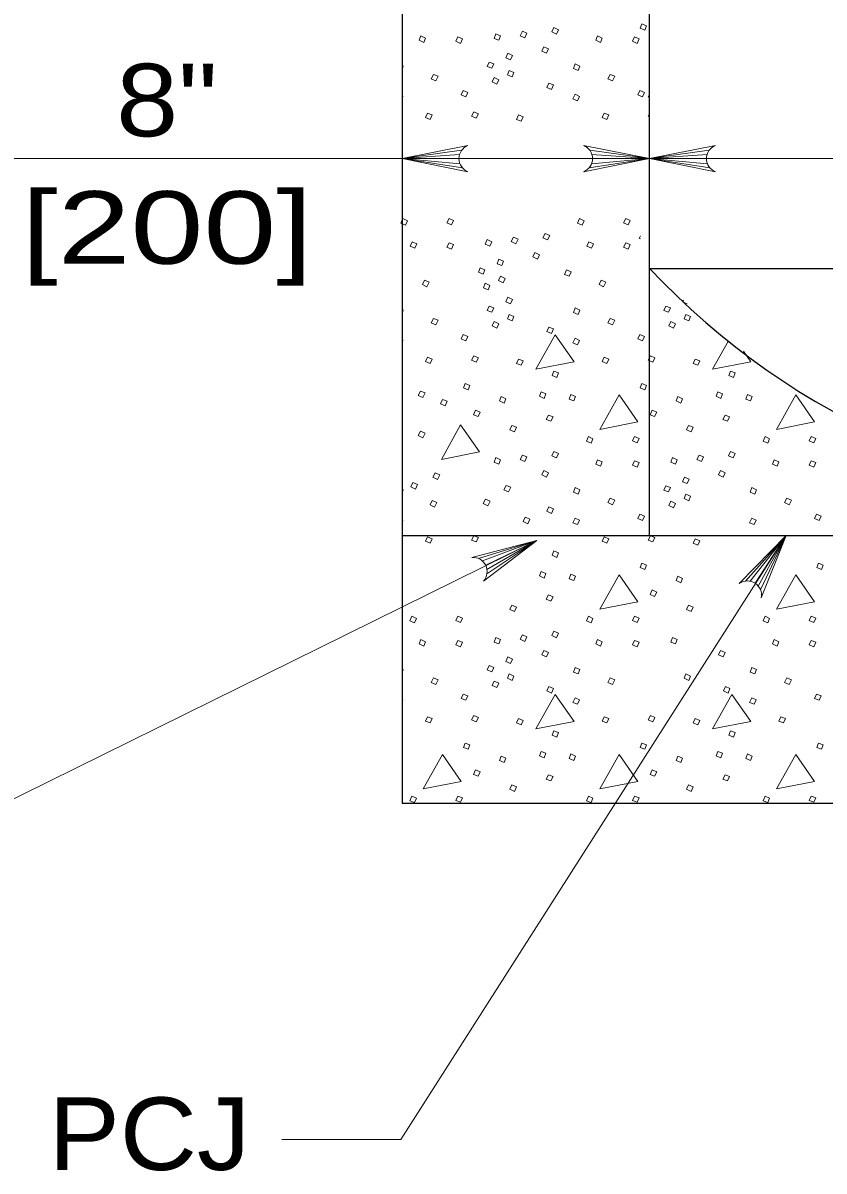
# Model space of a CAD drawing. Extents: x 1083.1 to 1123, y 697.4 to 741.4.
# Drawn here: x 1091.72 to 1093.443, y 720.889 to 723.357 of the extents above; entities that cross this region are included whole.
import ezdxf
from ezdxf.enums import TextEntityAlignment as Align

# ---------------------------------------------------------------- set-up
doc = ezdxf.new("R2010")
doc.units = 0
doc.header["$LTSCALE"] = 0.062
doc.layers.add('1', color=7, linetype='Continuous', lineweight=13)

msp = doc.modelspace()

# ---------------------------------------------------------------- linework, layer by layer
at = {"layer": '1', "lineweight": 25}
for p, q in [((1093.0675, 722.82933), (1093.0675, 724.8505)), ((1093.0675, 722.82933), (1095.442, 722.82933)), ((1093.0675, 722.25542), (1093.0675, 722.82933)), ((1092.53542, 722.25542), (1095.96625, 722.25542))]:
    msp.add_line(p, q, dxfattribs=at)
at = {"layer": '1'}
for p, q in [((1091.67708, 723.06533), (1093.0675, 723.06533)), ((1092.66358, 723.08333), (1092.53542, 723.06533)), ((1092.65925, 723.07442), (1092.53542, 723.06533)), ((1092.65792, 723.06533), (1092.53542, 723.06533)), ((1092.66017, 723.05383), (1092.53542, 723.06533)), ((1092.66508, 723.0455), (1092.53542, 723.06533)), ((1092.93775, 723.0455), (1093.0675, 723.06533)), ((1092.93933, 723.08333), (1093.0675, 723.06533)), ((1092.94267, 723.05383), (1093.0675, 723.06533)), ((1092.94367, 723.07442), (1093.0675, 723.06533)), ((1092.945, 723.06533), (1093.0675, 723.06533)), ((1093.19567, 723.08333), (1093.0675, 723.06533)), ((1093.19133, 723.07442), (1093.0675, 723.06533)), ((1095.442, 723.06533), (1093.0675, 723.06533)), ((1093.19, 723.06533), (1093.0675, 723.06533)), ((1093.19225, 723.05383), (1093.0675, 723.06533)), ((1093.19717, 723.0455), (1093.0675, 723.06533)), ((1093.361, 722.25542), (1092.53317, 720.95708)), ((1093.27392, 722.15733), (1093.361, 722.25542)), ((1093.28358, 722.15692), (1093.361, 722.25542)), ((1093.29442, 722.15258), (1093.361, 722.25542)), ((1093.30133, 722.14658), (1093.361, 722.25542)), ((1093.30642, 722.13808), (1093.361, 722.25542)), ((1092.70017, 722.20583), (1092.8255, 722.24467)), ((1092.70817, 722.2005), (1092.8255, 722.24467)), ((1092.71525, 722.19117), (1092.8255, 722.24467)), ((1092.718, 722.18242), (1092.8255, 722.24467)), ((1092.718, 722.1725), (1092.8255, 722.24467)), ((1092.53317, 720.95708), (1092.27733, 720.95708))]:
    msp.add_line(p, q, dxfattribs=at)
at = {"layer": '1', "lineweight": 25}
msp.add_lwpolyline([(1093.0675, 725.37967), (1092.53542, 725.37967), (1092.53542, 721.67958), (1095.96625, 721.67958), (1095.96625, 725.37967)], dxfattribs=at)
at = {"layer": '1'}
for points in [[(1092.79408, 723.33892), (1092.80408, 723.33492), (1092.79942, 723.32492), (1092.78942, 723.32958)], [(1092.86208, 723.34692), (1092.87208, 723.34225), (1092.86742, 723.33292), (1092.85742, 723.33758)], [(1093.05133, 723.35483), (1093.06133, 723.35083), (1093.05733, 723.3415), (1093.04733, 723.3455)], [(1092.57617, 723.32892), (1092.58617, 723.32425), (1092.58217, 723.315), (1092.57217, 723.31958)], [(1092.6555, 723.32692), (1092.6655, 723.32292), (1092.66083, 723.313), (1092.65083, 723.31758)], [(1092.73742, 723.33358), (1092.74742, 723.32892), (1092.74342, 723.31958), (1092.73342, 723.32367)], [(1092.956, 723.32892), (1092.966, 723.32425), (1092.962, 723.315), (1092.952, 723.31958)], [(1093.03533, 723.32692), (1093.04533, 723.32292), (1093.04067, 723.313), (1093.03067, 723.31758)], [(1092.76275, 723.29167), (1092.77275, 723.287), (1092.76875, 723.27767), (1092.75875, 723.28167)], [(1092.84008, 723.30567), (1092.85008, 723.301), (1092.84608, 723.29167), (1092.83608, 723.29633)], [(1092.72275, 723.273), (1092.73275, 723.269), (1092.72875, 723.25967), (1092.71875, 723.26367)], [(1092.908, 723.269), (1092.918, 723.26433), (1092.914, 723.255), (1092.904, 723.259)], [(1092.60283, 723.24633), (1092.61283, 723.24233), (1092.60817, 723.23233), (1092.59817, 723.237)], [(1092.73342, 723.23967), (1092.74342, 723.235), (1092.73942, 723.22567), (1092.72942, 723.23033)], [(1092.76608, 723.255), (1092.77608, 723.25033), (1092.77208, 723.241), (1092.76208, 723.24567)], [(1092.98267, 723.24633), (1092.99267, 723.24233), (1092.988, 723.23233), (1092.978, 723.237)], [(1092.85075, 723.22767), (1092.86075, 723.22367), (1092.85675, 723.21367), (1092.84675, 723.21833)], [(1092.66683, 723.21167), (1092.67683, 723.20767), (1092.67283, 723.19833), (1092.66283, 723.20233)], [(1092.90733, 723.20367), (1092.91733, 723.199), (1092.91267, 723.18967), (1092.90267, 723.19367)], [(1093.04667, 723.21167), (1093.05667, 723.20767), (1093.05267, 723.19833), (1093.04267, 723.20233)], [(1092.6895, 723.16575), (1092.6995, 723.16175), (1092.69483, 723.15242), (1092.68483, 723.15642)], [(1092.59017, 723.16308), (1092.60017, 723.15908), (1092.59617, 723.14975), (1092.58617, 723.15375)], [(1092.78608, 723.15908), (1092.79608, 723.15508), (1092.79142, 723.14575), (1092.78142, 723.14975)], [(1092.97, 723.16308), (1092.98, 723.15908), (1092.976, 723.14975), (1092.966, 723.15375)], [(1092.53708, 722.9365), (1092.54708, 722.93183), (1092.54308, 722.9225), (1092.53308, 722.9265)], [(1092.63642, 722.9365), (1092.64642, 722.9325), (1092.64175, 722.92317), (1092.63175, 722.92717)], [(1092.91692, 722.9365), (1092.92692, 722.93183), (1092.92292, 722.9225), (1092.91292, 722.9265)], [(1093.01625, 722.9365), (1093.02617, 722.9325), (1093.02158, 722.92317), (1093.01158, 722.92717)], [(1092.775, 722.8965), (1092.785, 722.8925), (1092.78033, 722.8825), (1092.77033, 722.88717)], [(1092.843, 722.9045), (1092.85292, 722.89983), (1092.84833, 722.8905), (1092.83833, 722.89517)], [(1092.55708, 722.8865), (1092.56708, 722.88183), (1092.56308, 722.8725), (1092.55308, 722.87717)], [(1092.63642, 722.8845), (1092.64642, 722.8805), (1092.64175, 722.8705), (1092.63175, 722.87517)], [(1092.71833, 722.89117), (1092.72833, 722.8865), (1092.72433, 722.87717), (1092.71433, 722.88117)], [(1092.93692, 722.8865), (1092.94692, 722.88183), (1092.94292, 722.8725), (1092.93292, 722.87717)], [(1093.01625, 722.8845), (1093.02617, 722.8805), (1093.02158, 722.8705), (1093.01158, 722.87517)], [(1092.74367, 722.84925), (1092.75367, 722.84458), (1092.74967, 722.83525), (1092.73967, 722.83925)], [(1092.821, 722.86317), (1092.831, 722.8585), (1092.827, 722.84925), (1092.817, 722.85392)], [(1092.70367, 722.83058), (1092.71367, 722.82658), (1092.70967, 722.81725), (1092.69967, 722.82125)], [(1092.88892, 722.82658), (1092.89892, 722.82192), (1092.89492, 722.81258), (1092.88492, 722.81658)], [(1092.58375, 722.80392), (1092.59375, 722.79992), (1092.58908, 722.78992), (1092.57908, 722.79458)], [(1092.71433, 722.79725), (1092.72433, 722.79258), (1092.72033, 722.78325), (1092.71033, 722.78792)], [(1092.747, 722.81258), (1092.757, 722.80792), (1092.753, 722.79858), (1092.743, 722.80325)], [(1092.96358, 722.80392), (1092.97358, 722.79992), (1092.96892, 722.78992), (1092.95892, 722.79458)], [(1092.72275, 722.7485), (1092.73275, 722.7445), (1092.72875, 722.73517), (1092.71875, 722.73917)], [(1092.76275, 722.76717), (1092.77275, 722.7625), (1092.76875, 722.75317), (1092.75875, 722.75717)], [(1092.908, 722.7445), (1092.918, 722.73983), (1092.914, 722.7305), (1092.904, 722.7345)], [(1093.10258, 722.7485), (1093.11258, 722.7445), (1093.10858, 722.73517), (1093.09858, 722.73917)], [(1092.60283, 722.72183), (1092.61283, 722.71783), (1092.60817, 722.70783), (1092.59817, 722.7125)], [(1092.76608, 722.7305), (1092.77608, 722.72583), (1092.77208, 722.7165), (1092.76208, 722.72117)], [(1092.98267, 722.72183), (1092.99267, 722.71783), (1092.988, 722.70783), (1092.978, 722.7125)], [(1093.14592, 722.7305), (1093.15592, 722.72583), (1093.15192, 722.7165), (1093.14192, 722.72117)], [(1092.73342, 722.71517), (1092.74342, 722.7105), (1092.73942, 722.70117), (1092.72942, 722.70583)], [(1092.85075, 722.70317), (1092.86075, 722.69917), (1092.85675, 722.68917), (1092.84675, 722.69383)], [(1093.11325, 722.71517), (1093.12325, 722.7105), (1093.11925, 722.70117), (1093.10925, 722.70583)], [(1092.66683, 722.68717), (1092.67683, 722.68317), (1092.67283, 722.67383), (1092.66283, 722.67783)], [(1092.86475, 722.6865), (1092.82342, 722.61258), (1092.90533, 722.62858)], [(1092.90733, 722.67917), (1092.91733, 722.6745), (1092.91267, 722.66525), (1092.90267, 722.66917)], [(1093.04667, 722.68717), (1093.05667, 722.68317), (1093.05267, 722.67383), (1093.04267, 722.67783)], [(1092.59017, 722.63858), (1092.60017, 722.63458), (1092.59617, 722.62525), (1092.58617, 722.62925)], [(1092.6895, 722.64125), (1092.6995, 722.63725), (1092.69483, 722.62792), (1092.68483, 722.63192)], [(1092.78608, 722.63458), (1092.79608, 722.63058), (1092.79142, 722.62125), (1092.78142, 722.62525)], [(1092.97, 722.63858), (1092.98, 722.63458), (1092.976, 722.62525), (1092.966, 722.62925)], [(1093.06933, 722.64125), (1093.07925, 722.63725), (1093.07458, 722.62792), (1093.06458, 722.63192)], [(1093.16592, 722.63458), (1093.17592, 722.63058), (1093.17125, 722.62125), (1093.16125, 722.62525)], [(1092.86208, 722.60858), (1092.87208, 722.60458), (1092.86808, 722.59458), (1092.85808, 722.59925)], [(1093.24192, 722.60858), (1093.25183, 722.60458), (1093.24783, 722.59458), (1093.23783, 722.59925)], [(1092.6715, 722.58192), (1092.6815, 722.57792), (1092.6775, 722.56858), (1092.6675, 722.57258)], [(1093.05133, 722.58192), (1093.06133, 722.57792), (1093.05733, 722.56858), (1093.04733, 722.57258)], [(1092.57483, 722.56567), (1092.58483, 722.56167), (1092.58017, 722.55167), (1092.57017, 722.55633)], [(1092.6225, 722.54783), (1092.6325, 722.54383), (1092.62783, 722.53383), (1092.61783, 722.5385)], [(1092.74875, 722.55392), (1092.75875, 722.54925), (1092.75475, 722.53992), (1092.74475, 722.54458)], [(1092.83475, 722.56392), (1092.84475, 722.55992), (1092.84075, 722.54992), (1092.83075, 722.55458)], [(1092.89867, 722.55858), (1092.90867, 722.55392), (1092.90467, 722.54458), (1092.89467, 722.54858)], [(1093.002, 722.55725), (1092.96067, 722.48333), (1093.04267, 722.49933)], [(1093.12858, 722.55392), (1093.13858, 722.54925), (1093.13458, 722.53992), (1093.12458, 722.54458)], [(1093.21458, 722.56392), (1093.22458, 722.55992), (1093.22058, 722.54992), (1093.21058, 722.55458)], [(1093.2785, 722.55858), (1093.2885, 722.55392), (1093.2845, 722.54458), (1093.2745, 722.54858)], [(1093.38183, 722.55725), (1093.3405, 722.48333), (1093.42242, 722.49933)], [(1092.6935, 722.52458), (1092.7035, 722.52), (1092.69883, 722.51067), (1092.68883, 722.51467)], [(1093.07325, 722.52458), (1093.08325, 722.52), (1093.07858, 722.51067), (1093.06858, 722.51467)], [(1092.85008, 722.51392), (1092.86008, 722.51), (1092.85542, 722.50067), (1092.84542, 722.50467)], [(1093.22992, 722.51392), (1093.23983, 722.51), (1093.23525, 722.50067), (1093.22525, 722.50467)], [(1092.57483, 722.47925), (1092.58483, 722.47525), (1092.58017, 722.46525), (1092.57017, 722.46992)], [(1092.66133, 722.49283), (1092.62008, 722.41883), (1092.702, 722.43483)], [(1092.77142, 722.492), (1092.78142, 722.488), (1092.77742, 722.478), (1092.76742, 722.48267)], [(1093.15125, 722.492), (1093.16125, 722.488), (1093.15725, 722.478), (1093.14725, 722.48267)], [(1092.936, 722.468), (1092.946, 722.46333), (1092.942, 722.454), (1092.932, 722.458)], [(1093.03533, 722.468), (1093.04533, 722.464), (1093.04067, 722.45467), (1093.03067, 722.45867)], [(1093.31583, 722.468), (1093.32583, 722.46333), (1093.32183, 722.454), (1093.31183, 722.458)], [(1093.41517, 722.468), (1093.42508, 722.464), (1093.4205, 722.45467), (1093.4105, 722.45867)], [(1092.79408, 722.428), (1092.80408, 722.424), (1092.79942, 722.414), (1092.78942, 722.41867)], [(1092.86208, 722.436), (1092.87208, 722.43133), (1092.86742, 722.422), (1092.85742, 722.42667)], [(1093.17392, 722.428), (1093.18392, 722.424), (1093.17925, 722.414), (1093.16925, 722.41867)], [(1093.24192, 722.436), (1093.25183, 722.43133), (1093.24717, 722.422), (1093.23725, 722.42667)], [(1092.73742, 722.42267), (1092.74742, 722.418), (1092.74342, 722.40867), (1092.73342, 722.41267)], [(1092.956, 722.418), (1092.966, 722.41333), (1092.962, 722.404), (1092.952, 722.40867)], [(1093.03533, 722.416), (1093.04533, 722.412), (1093.04067, 722.402), (1093.03067, 722.40667)], [(1093.11725, 722.42267), (1093.12725, 722.418), (1093.12325, 722.40867), (1093.11325, 722.41267)], [(1093.33583, 722.418), (1093.34583, 722.41333), (1093.34183, 722.404), (1093.33183, 722.40867)], [(1093.41517, 722.416), (1093.42508, 722.412), (1093.4205, 722.402), (1093.4105, 722.40667)], [(1092.60658, 722.38983), (1092.61658, 722.38583), (1092.61192, 722.37583), (1092.60192, 722.3805)], [(1092.84008, 722.39467), (1092.85008, 722.39), (1092.84608, 722.38067), (1092.83608, 722.38533)], [(1093.14258, 722.38067), (1093.15258, 722.376), (1093.14858, 722.36675), (1093.13858, 722.37067)], [(1093.21992, 722.39467), (1093.22992, 722.39), (1093.22592, 722.38067), (1093.21592, 722.38533)], [(1092.55892, 722.369), (1092.56892, 722.365), (1092.56425, 722.355), (1092.55425, 722.35967)], [(1092.75908, 722.363), (1092.76908, 722.359), (1092.76442, 722.349), (1092.75442, 722.35367)], [(1092.908, 722.35808), (1092.918, 722.35342), (1092.914, 722.34408), (1092.904, 722.34808)], [(1093.10258, 722.36208), (1093.11258, 722.35808), (1093.10858, 722.34875), (1093.09858, 722.35275)], [(1093.28783, 722.35808), (1093.29783, 722.35342), (1093.29383, 722.34408), (1093.28383, 722.34808)], [(1092.60025, 722.33025), (1092.61025, 722.32625), (1092.60558, 722.31625), (1092.59558, 722.32092)], [(1092.71458, 722.33325), (1092.72458, 722.32925), (1092.71992, 722.31925), (1092.71, 722.32392)], [(1092.98267, 722.33542), (1092.99267, 722.33142), (1092.988, 722.32142), (1092.978, 722.32608)], [(1093.11325, 722.32875), (1093.12325, 722.32408), (1093.11925, 722.31475), (1093.10925, 722.31942)], [(1093.14592, 722.34408), (1093.15592, 722.33942), (1093.15192, 722.33008), (1093.14192, 722.33475)], [(1093.3625, 722.33542), (1093.3725, 722.33142), (1093.36783, 722.32142), (1093.35783, 722.32608)], [(1092.85075, 722.31675), (1092.86075, 722.31275), (1092.85675, 722.30275), (1092.84675, 722.30742)], [(1093.04667, 722.30075), (1093.05667, 722.29675), (1093.05267, 722.28742), (1093.04267, 722.29142)], [(1093.42642, 722.30075), (1093.43642, 722.29675), (1093.43242, 722.28742), (1093.42242, 722.29142)], [(1092.80042, 722.2945), (1092.81042, 722.2905), (1092.80575, 722.2805), (1092.79575, 722.28517)], [(1092.90733, 722.29275), (1092.91733, 722.28808), (1092.91267, 722.27875), (1092.90267, 722.28275)], [(1093.28717, 722.29275), (1093.29717, 722.28808), (1093.2925, 722.27875), (1093.2825, 722.28275)], [(1092.59017, 722.25208), (1092.60017, 722.24808), (1092.59617, 722.23875), (1092.58617, 722.24275)], [(1092.6895, 722.25475), (1092.6995, 722.25075), (1092.69483, 722.24142), (1092.68483, 722.24542)], [(1092.97, 722.25208), (1092.98, 722.24808), (1092.976, 722.23875), (1092.966, 722.24275)], [(1093.06933, 722.25475), (1093.07925, 722.25075), (1093.07458, 722.24142), (1093.06458, 722.24542)], [(1093.16592, 722.24808), (1093.17592, 722.24408), (1093.17125, 722.23475), (1093.16125, 722.23875)], [(1092.86208, 722.22217), (1092.87208, 722.21817), (1092.86808, 722.20817), (1092.85808, 722.21283)], [(1092.83475, 722.1775), (1092.84475, 722.1735), (1092.84075, 722.1635), (1092.83075, 722.16817)], [(1093.05133, 722.1955), (1093.06133, 722.1915), (1093.05733, 722.18217), (1093.04733, 722.18617)], [(1093.43108, 722.1955), (1093.44108, 722.1915), (1093.43708, 722.18217), (1093.42708, 722.18617)], [(1092.89867, 722.17217), (1092.90867, 722.1675), (1092.90467, 722.15817), (1092.89467, 722.16217)], [(1093.002, 722.17083), (1092.96067, 722.09683), (1093.04267, 722.11283)], [(1093.12858, 722.1675), (1093.13858, 722.16283), (1093.13458, 722.1535), (1093.12458, 722.15817)], [(1093.38183, 722.17083), (1093.3405, 722.09683), (1093.42242, 722.11283)], [(1092.85008, 722.1275), (1092.86008, 722.1235), (1092.85542, 722.11417), (1092.84542, 722.11817)], [(1093.07325, 722.13817), (1093.08325, 722.1335), (1093.07858, 722.12417), (1093.06858, 722.12817)], [(1092.77142, 722.1055), (1092.78142, 722.1015), (1092.77742, 722.0915), (1092.76742, 722.09617)], [(1093.15125, 722.1055), (1093.16125, 722.1015), (1093.15725, 722.0915), (1093.14725, 722.09617)], [(1092.55617, 722.08158), (1092.56617, 722.07692), (1092.56217, 722.06758), (1092.55217, 722.07158)], [(1092.6555, 722.08158), (1092.6655, 722.07758), (1092.66083, 722.06825), (1092.65083, 722.07225)], [(1092.936, 722.08158), (1092.946, 722.07692), (1092.942, 722.06758), (1092.932, 722.07158)], [(1093.03533, 722.08158), (1093.04533, 722.07758), (1093.04067, 722.06825), (1093.03067, 722.07225)], [(1093.31583, 722.08158), (1093.32583, 722.07692), (1093.32183, 722.06758), (1093.31183, 722.07158)], [(1093.41517, 722.08158), (1093.42508, 722.07758), (1093.4205, 722.06825), (1093.4105, 722.07225)], [(1092.57617, 722.03158), (1092.58617, 722.02692), (1092.58217, 722.01758), (1092.57217, 722.02225)], [(1092.6555, 722.02958), (1092.6655, 722.02558), (1092.66083, 722.01558), (1092.65083, 722.02025)], [(1092.73742, 722.03625), (1092.74742, 722.03158), (1092.74342, 722.02225), (1092.73342, 722.02625)], [(1092.79408, 722.04158), (1092.80408, 722.03758), (1092.79942, 722.02758), (1092.78942, 722.03225)], [(1092.86208, 722.04958), (1092.87208, 722.04492), (1092.86742, 722.03558), (1092.85742, 722.04025)], [(1092.956, 722.03158), (1092.966, 722.02692), (1092.962, 722.01758), (1092.952, 722.02225)], [(1093.03533, 722.02958), (1093.04533, 722.02558), (1093.04067, 722.01558), (1093.03067, 722.02025)], [(1093.11725, 722.03625), (1093.12725, 722.03158), (1093.12325, 722.02225), (1093.11325, 722.02625)], [(1093.33583, 722.03158), (1093.34583, 722.02692), (1093.34183, 722.01758), (1093.33183, 722.02225)], [(1093.41517, 722.02958), (1093.42508, 722.02558), (1093.4205, 722.01558), (1093.4105, 722.02025)], [(1092.84008, 722.00825), (1092.85008, 722.00358), (1092.84608, 721.99425), (1092.83608, 721.99892)], [(1093.21992, 722.00825), (1093.22992, 722.00358), (1093.22592, 721.99425), (1093.21592, 721.99892)], [(1092.76275, 721.99425), (1092.77275, 721.98958), (1092.76875, 721.98025), (1092.75875, 721.98425)], [(1092.72275, 721.97558), (1092.73275, 721.97158), (1092.72875, 721.96225), (1092.71875, 721.96625)], [(1092.76608, 721.95758), (1092.77608, 721.95292), (1092.77208, 721.94358), (1092.76208, 721.94825)], [(1092.908, 721.97158), (1092.918, 721.96692), (1092.914, 721.95758), (1092.904, 721.96158)], [(1093.14592, 721.95758), (1093.15592, 721.95292), (1093.15192, 721.94358), (1093.14192, 721.94825)], [(1093.28783, 721.97158), (1093.29783, 721.96692), (1093.29383, 721.95758), (1093.28383, 721.96158)], [(1092.60283, 721.94892), (1092.61283, 721.94492), (1092.60817, 721.935), (1092.59817, 721.93958)], [(1092.73342, 721.94225), (1092.74342, 721.93758), (1092.73942, 721.92833), (1092.72942, 721.933)], [(1092.85075, 721.93033), (1092.86075, 721.92633), (1092.85675, 721.91633), (1092.84675, 721.921)], [(1092.98267, 721.94892), (1092.99267, 721.94492), (1092.988, 721.935), (1092.978, 721.93958)], [(1093.23058, 721.93033), (1093.2405, 721.92633), (1093.23658, 721.91633), (1093.22658, 721.921)], [(1093.3625, 721.94892), (1093.3725, 721.94492), (1093.36783, 721.935), (1093.35783, 721.93958)], [(1092.66683, 721.91433), (1092.67683, 721.91033), (1092.67283, 721.901), (1092.66283, 721.905)], [(1092.86475, 721.91367), (1092.82342, 721.83967), (1092.90533, 721.85567)], [(1092.90733, 721.90633), (1092.91733, 721.90167), (1092.91267, 721.89233), (1092.90267, 721.89633)], [(1093.24458, 721.91367), (1093.20325, 721.83967), (1093.28517, 721.85567)], [(1093.28717, 721.90633), (1093.29717, 721.90167), (1093.2925, 721.89233), (1093.2825, 721.89633)], [(1093.42642, 721.91433), (1093.43642, 721.91033), (1093.43242, 721.901), (1093.42242, 721.905)], [(1092.59017, 721.86567), (1092.60017, 721.86167), (1092.59617, 721.85233), (1092.58617, 721.85633)], [(1092.6895, 721.86833), (1092.6995, 721.86433), (1092.69483, 721.855), (1092.68483, 721.859)], [(1092.78608, 721.86167), (1092.79608, 721.85767), (1092.79142, 721.84833), (1092.78142, 721.85233)], [(1092.97, 721.86567), (1092.98, 721.86167), (1092.976, 721.85233), (1092.966, 721.85633)], [(1093.06933, 721.86833), (1093.07925, 721.86433), (1093.07458, 721.855), (1093.06458, 721.859)], [(1093.16592, 721.86167), (1093.17592, 721.85767), (1093.17125, 721.84833), (1093.16125, 721.85233)], [(1093.34983, 721.86567), (1093.35983, 721.86167), (1093.35583, 721.85233), (1093.34583, 721.85633)], [(1092.86208, 721.83567), (1092.87208, 721.83167), (1092.86808, 721.82167), (1092.85808, 721.82633)], [(1093.24192, 721.83567), (1093.25183, 721.83167), (1093.24783, 721.82167), (1093.23783, 721.82633)], [(1092.6715, 721.809), (1092.6815, 721.805), (1092.6775, 721.79567), (1092.6675, 721.79967)], [(1093.05133, 721.809), (1093.06133, 721.805), (1093.05733, 721.79567), (1093.04733, 721.79967)], [(1093.43108, 721.809), (1093.44108, 721.805), (1093.43708, 721.79567), (1093.42708, 721.79967)], [(1092.62217, 721.78442), (1092.58083, 721.71042), (1092.66283, 721.72642)], [(1092.83475, 721.79108), (1092.84475, 721.78708), (1092.84075, 721.77708), (1092.83075, 721.78175)], [(1092.89867, 721.78575), (1092.90867, 721.78108), (1092.90467, 721.77175), (1092.89467, 721.77575)], [(1093.002, 721.78442), (1092.96067, 721.71042), (1093.04267, 721.72642)], [(1093.21458, 721.79108), (1093.22458, 721.78708), (1093.22058, 721.77708), (1093.21058, 721.78175)], [(1093.2785, 721.78575), (1093.2885, 721.78108), (1093.2845, 721.77175), (1093.2745, 721.77575)], [(1093.38183, 721.78442), (1093.3405, 721.71042), (1093.42242, 721.72642)], [(1092.74875, 721.78108), (1092.75875, 721.77642), (1092.75475, 721.76708), (1092.74475, 721.77175)], [(1093.12858, 721.78108), (1093.13858, 721.77642), (1093.13458, 721.76708), (1093.12458, 721.77175)], [(1092.6935, 721.75175), (1092.7035, 721.74708), (1092.69883, 721.73775), (1092.68883, 721.74175)], [(1092.85008, 721.74108), (1092.86008, 721.73708), (1092.85542, 721.72775), (1092.84542, 721.73175)], [(1093.07325, 721.75175), (1093.08325, 721.74708), (1093.07858, 721.73775), (1093.06858, 721.74175)], [(1093.22992, 721.74108), (1093.23983, 721.73708), (1093.23525, 721.72775), (1093.22525, 721.73175)], [(1092.77142, 721.71908), (1092.78142, 721.71508), (1092.77742, 721.70508), (1092.76742, 721.70975)], [(1093.15125, 721.71908), (1093.16125, 721.71508), (1093.15725, 721.70508), (1093.14725, 721.70975)], [(1092.55617, 721.69508), (1092.56617, 721.69042), (1092.56217, 721.68108), (1092.55217, 721.68508)], [(1092.6555, 721.69508), (1092.6655, 721.69108), (1092.66083, 721.68175), (1092.65083, 721.68575)], [(1092.936, 721.69508), (1092.946, 721.69042), (1092.942, 721.68108), (1092.932, 721.68508)], [(1093.03533, 721.69508), (1093.04533, 721.69108), (1093.04067, 721.68175), (1093.03067, 721.68575)], [(1093.31583, 721.69508), (1093.32583, 721.69042), (1093.32183, 721.68108), (1093.31183, 721.68508)], [(1093.41517, 721.69508), (1093.42508, 721.69108), (1093.4205, 721.68175), (1093.4105, 721.68575)]]:
    msp.add_lwpolyline(points, close=True, dxfattribs=at)
for points in [[(1092.53542, 723.26567), (1092.53817, 723.26433), (1092.53542, 723.25775)], [(1092.53542, 723.2), (1092.5375, 723.199), (1092.53542, 723.19475)], [(1093.0675, 723.19717), (1093.06458, 723.19833), (1093.0675, 723.20408)], [(1093.0675, 723.15525), (1093.06458, 723.15642), (1093.0675, 723.16208)], [(1092.677, 723.037), (1092.53542, 723.06533), (1092.677, 723.09367)], [(1092.92592, 723.037), (1093.0675, 723.06533), (1092.92592, 723.09367)], [(1093.20908, 723.037), (1093.0675, 723.06533), (1093.20908, 723.09367)], [(1093.04842, 722.89283), (1093.0455, 722.89392), (1093.04842, 722.89967)], [(1093.14875, 722.7535), (1093.14858, 722.75317), (1093.13858, 722.75717), (1093.14025, 722.76133)], [(1092.53542, 722.74117), (1092.53817, 722.73983), (1092.53542, 722.73333)], [(1092.53542, 722.6755), (1092.5375, 722.6745), (1092.53542, 722.67025)], [(1093.2375, 722.67383), (1093.20325, 722.61258), (1093.28517, 722.62858), (1093.26925, 722.65125)], [(1092.53542, 722.35475), (1092.53817, 722.35342), (1092.53542, 722.34683)], [(1092.53542, 722.28908), (1092.5375, 722.28808), (1092.53542, 722.28383)], [(1093.26033, 722.152), (1093.361, 722.25542), (1093.30783, 722.12117)], [(1092.8255, 722.24467), (1091.13508, 721.41017), (1090.62667, 721.41017)], [(1092.68575, 722.20825), (1092.8255, 722.24467), (1092.7105, 722.15733)], [(1092.53542, 721.96825), (1092.53817, 721.96692), (1092.53542, 721.96042)], [(1092.53542, 721.90267), (1092.5375, 721.90167), (1092.53542, 721.89742)]]:
    msp.add_lwpolyline(points, dxfattribs=at)
for centre, start, end in [((1092.68844, 723.06539), 112.08782, 247.91395), ((1092.91446, 723.06539), 292.08605, 67.91218), ((1093.22053, 723.06539), 112.08782, 247.91395), ((1092.68783, 722.17778), 317.98606, 93.81218), ((1093.2779, 722.12696), 349.171, 124.99712)]:
    msp.add_arc(centre, 0.03056, start, end, dxfattribs=at)
at = {"layer": '1', "lineweight": 25}
msp.add_ellipse((1094.25476, 723.9448), major_axis=(-1.62917, 0), ratio=0.999895, start_param=0.7542896, end_param=2.387303, dxfattribs=at)

# ---------------------------------------------------------------- texts
at = {"layer": '1'}
for s, width, p in [('8"', 1.15, (1092.03, 723.11325)), ('[200]', 1.35, (1092.03, 722.83925))]:
    msp.add_text(s, height=0.156, dxfattribs=dict(at, width=width)).set_placement(p, align=Align.CENTER)
at = {"layer": '1', "width": 1.1}
msp.add_text('PCJ', height=0.156, dxfattribs=at).set_placement((1091.77567, 720.89133))

doc.saveas('drawing.dxf')
